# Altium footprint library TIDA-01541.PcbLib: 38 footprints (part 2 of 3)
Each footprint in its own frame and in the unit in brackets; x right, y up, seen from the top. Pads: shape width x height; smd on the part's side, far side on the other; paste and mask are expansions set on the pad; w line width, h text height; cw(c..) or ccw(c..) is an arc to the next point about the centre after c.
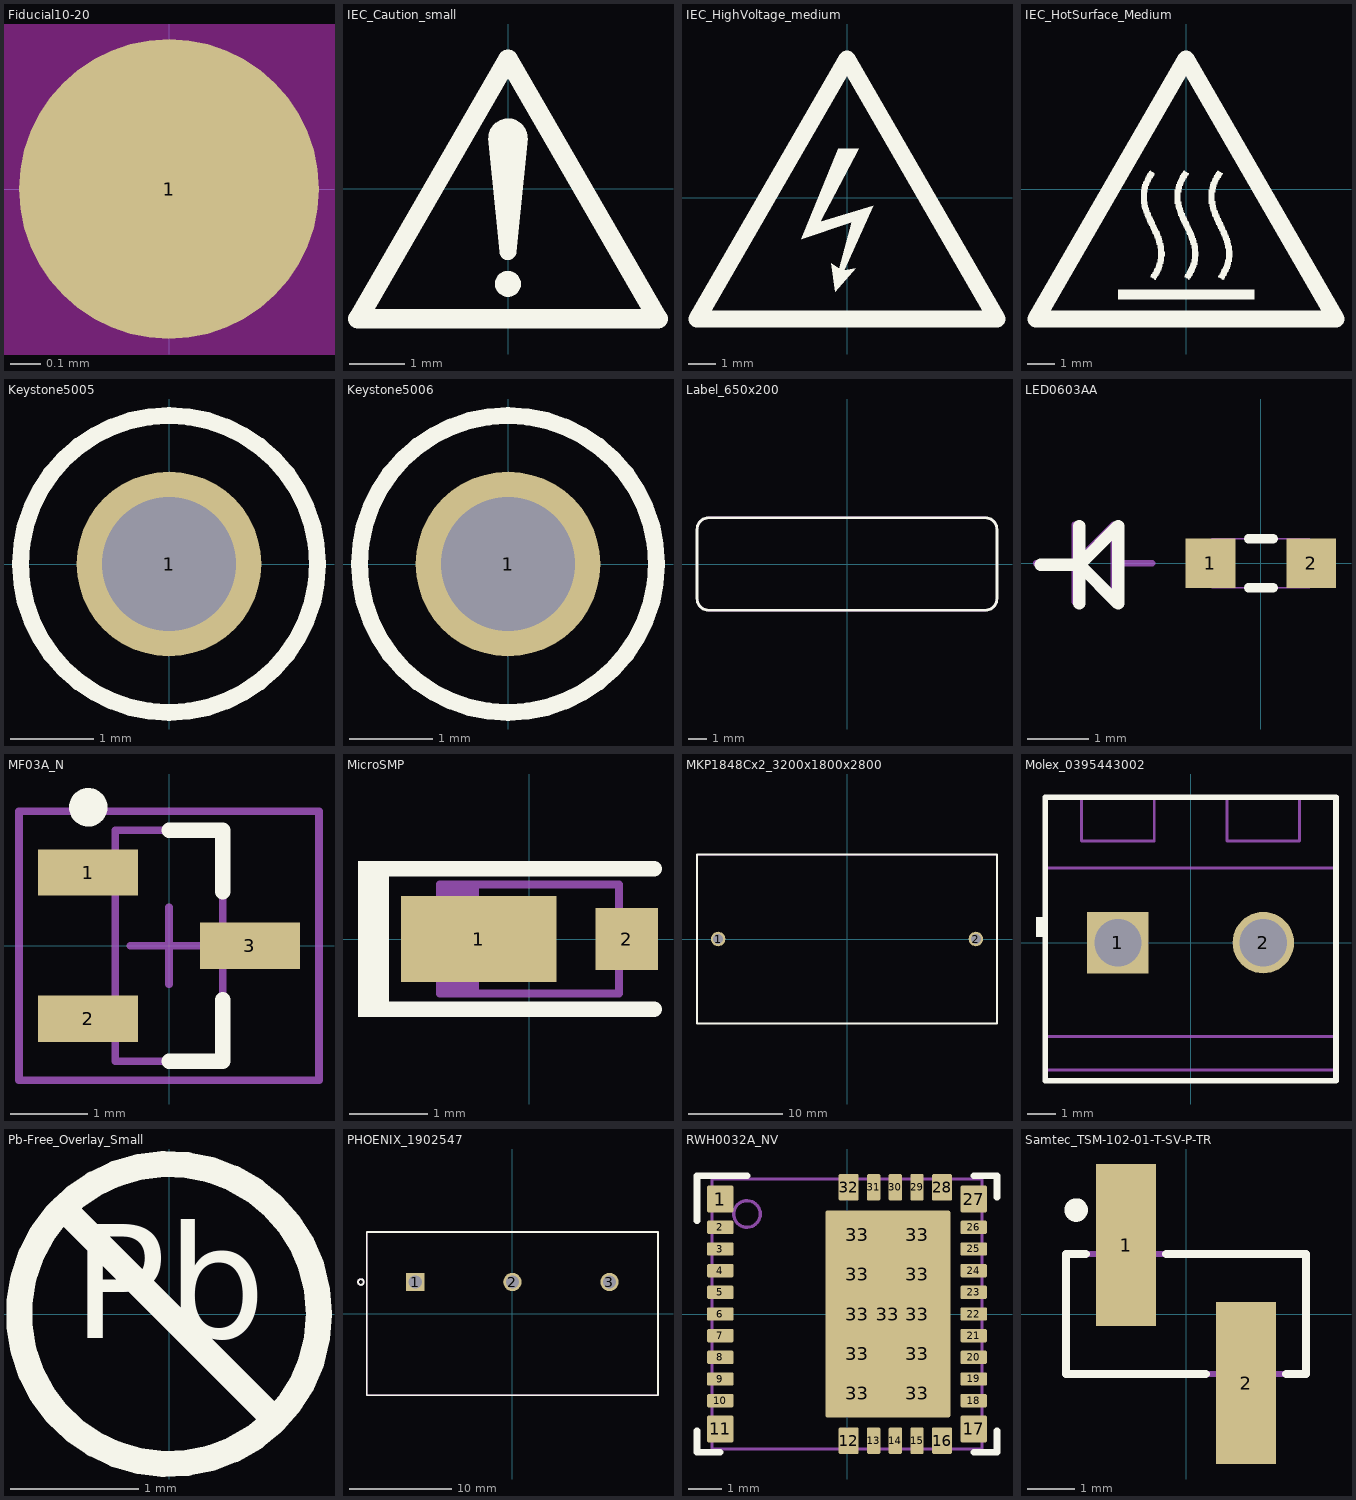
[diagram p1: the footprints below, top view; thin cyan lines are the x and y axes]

## Fiducial10-20 [mm]
pads (1):
  round 1 smd mask+0.5: 1(0,0)
Top Layer keep-out:
  circle w1.178: c0,0 r0.5

## IEC_Caution_small [mm]
height 8.382
Top Overlay:
  circle w0.254: c0,-1.143 r0.025
  circle w0.356: c0,0.914 r0.178
  circle w0.254: c0,-1.727 r0.108
  region: -0.356,0.914 0.356,0.914 0.152,-1.143 -0.152,-1.143
  lines w0.356: -2.718,-2.362 2.718,-2.362 0,2.345 -2.718,-2.362

## IEC_HighVoltage_medium [mm]
Top Overlay:
  region: -0.33,1.803 0.432,1.803 -0.991,-0.889 0.965,-0.305 -0.102,-2.667 0.33,-2.591 -0.432,-3.454 -0.584,-2.413 -0.279,-2.616 0.178,-0.914 -1.676,-1.524
  lines w0.635: -5.512,-4.458 0,5.089 5.512,-4.458 -5.512,-4.458

## IEC_HotSurface_Medium [mm]
height 8.382
Top Overlay:
  drawing of 7 lines, arcs and shapes, not listed

## Keystone5005 [mil] "Keystone Compact loops"
height 220
pads (1):
  round 87 hole 63: 1(0,0)
Top Overlay:
  circle w7.99: c0,0 r70
Mechanical 5:
  circle w5: c0,0 r70.71
  text ".Designator" at -55,-15 h30
3D body "Keystone_5005.stp": height 225.2, standoff -129.92, extent -63,-63 62.49,62.74

## Keystone5006 [mil] "Keystone Compact loops"
height 220
pads (1):
  round 87 hole 63: 1(0,0)
Top Overlay:
  circle w7.99: c0,0 r70
Mechanical 5:
  circle w5: c0,0 r70.71
  text ".Designator" at -55,-15 h30
3D body "Keystone_5006.stp": height 225.2, standoff -129.92, extent -63,-63 62.49,62.74

## Label_650x200 [mm] "Thermal Transfer Label"
height 0.025
Top Overlay:
  lines w0.152: -8.255,-1.905 ccw(c-7.62,-1.905) -7.62,-2.54 7.62,-2.54 ccw(c7.62,-1.905) 8.255,-1.905 8.255,1.905 ccw(c7.62,1.905) 7.62,2.54 -7.62,2.54 ccw(c-7.62,1.905) -8.255,1.905 -8.255,-1.905
Mechanical 5:
  lines w0.127: -8.255,-1.905 ccw(c-7.62,-1.905) -7.62,-2.54 7.62,-2.54 ccw(c7.62,-1.905) 8.255,-1.905 8.255,1.905 ccw(c7.62,1.905) 7.62,2.54 -7.62,2.54 ccw(c-7.62,1.905) -8.255,1.905 -8.255,-1.905
  text ".Designator" at -1.524,-0.508 h1.02
3D body: height 0.03, standoff 0, extent -8.256,-2.541 8.256,2.541

## LED0603AA [mil]
height 35.43
pads (2):
  rect 32x32 smd: 1(-32.48,0) 2(32.48,0)
Top Overlay:
  lines w6: -8,-15.75 8,-15.75 ; -8,15.75 8,15.75
  lines w8: -142,-1 -117,-1 ; -117,-26 -117,24 ; -117,-1 -92,-26 -92,24 -117,-1
Mechanical 5:
  lines w1: -31.5,-15.75 31.5,-15.75 31.5,15.75 -31.5,15.75 -31.5,-15.75
  lines w3.94: -145,0 -120,0 ; -120,-25 -120,25 ; -95,0 -70,0 ; -120,0 -95,25 -95,-25 -120,0
  text ".Designator" at 0,-5 h30

## MF03A_N [mm] "SOT23, 3-Leads, Body 2.9x1.3mm, Pitch 0.95mm, Lead Span 2.4mm, IPC Medium Density"
height 1.12
pads (3):
  rect 1.3x0.6 smd: 1(-1.05,0.95) 2(-1.05,-0.95) 3(1.05,0)
Top Overlay:
  circle w0.25: c-1.05,1.8 r0.125
  lines w0.2: 0,-1.5 0.7,-1.5 0.7,-0.7 ; 0,1.5 0.7,1.5 0.7,0.7
Mechanical 5:
  text ".Designator" at -0.051,-0.61 h0.76
Mechanical 13:
  lines w0.1: -0.7,-1.5 -0.7,1.5 0.7,1.5 0.7,-1.5 -0.7,-1.5
Mechanical 15:
  lines w0.1: -0.5,0 0.5,0 ; 0,-0.5 0,0.5 ; -1.95,-1.75 -1.95,1.75 1.95,1.75 1.95,-1.75 -1.95,-1.75
3D body: height 1.12, standoff 0, extent -0.7,-1.5 0.7,1.5

## MicroSMP [mm] "SMD, 2-Leads, Body 2.2x1.3mm"
height 0.73
pads (2):
  rect 2x1.1 smd: 1(-0.65,0)
  rect 0.8x0.8 smd: 2(1.25,0)
Top Overlay:
  rectangle: -2.2,-1 -1.9,1
  lines w0.2: 1.6,-0.9 -1.9,-0.9 -1.9,0.9 1.6,0.9
Mechanical 5:
  rectangle: -1.15,-0.7 -0.7,0.7
  lines w0.1: -0.7,-0.7 -0.7,0.7 ; -1.15,-0.7 -1.15,0.7 1.15,0.7 1.15,-0.7 -1.15,-0.7
  text ".Designator" at -0.279,-0.33 h0.76
3D body: height 0.75, standoff 0.73, extent -0.9,-0.7 -0.7,0.7
3D body: height 0.73, standoff 0, extent -1.15,-0.7 1.15,0.7

## MKP1848Cx2_3200x1800x2800 [mm] "TH, 2-Leads, Body 32x18mm"
height 28
pads (2):
  round 1.55 hole 1.05: 1(-13.75,0) 2(13.75,0)
Top Overlay:
  lines w0.2: -16,-9 16,-9 16,9 -16,9 -16,-9
Mechanical 5:
  lines w0.1: -16,-9 -16,9 16,9 16,-9 -16,-9
  text ".Designator" at 0.051,1.295 h0.76
3D body: height 28, standoff 0, extent -16,-9 16,9
3D body: height 0, standoff -3, extent 13.35,-0.4 14.15,0.4
3D body: height 0, standoff -3, extent -14.15,-0.4 -13.35,0.4

## Molex_0395443002 [mm] "Terminal Block, 5.08mm, 2x1, TH"
height 14.7
pads (2):
  rect 2.15x2.15 hole 1.65: 1(-2.54,0)
  round 2.15 hole 1.65: 2(2.54,0)
Top Overlay:
  rectangle: -5.4,0.2 -5.08,0.9
  lines w0.2: -5.08,-4.826 5.08,-4.826 5.08,-4.445 5.08,-3.281 5.08,2.61 5.08,5.08 3.81,5.08 1.27,5.08 -1.27,5.08 -3.81,5.08 -5.08,5.08 -5.08,2.61 -5.08,-3.281 -5.08,-4.445 -5.08,-4.826
Mechanical 5:
  lines w0.1: -5.08,-4.445 -5.08,-4.826 5.08,-4.826 5.08,-4.445 ; -5.08,-4.445 -5.08,-3.281 ; -5.08,-4.445 5.08,-4.445 ; -5.08,-3.281 -5.08,2.61 ; -5.08,-3.281 5.08,-3.281 ; -5.08,2.61 -5.08,5.08 -3.81,5.08 ; -5.08,2.61 5.08,2.61 ; -3.81,5.08 -1.27,5.08 ; -3.81,5.08 -3.81,3.556 -1.27,3.556 -1.27,5.08 ; -1.27,5.08 1.27,5.08 ; 1.27,5.08 3.81,5.08 ; 1.27,5.08 1.27,3.556 3.81,3.556 3.81,5.08 ; 3.81,5.08 5.08,5.08 5.08,2.61 ; 5.08,-4.445 5.08,-3.281 ; 5.08,-3.281 5.08,2.61
  text ".Designator" at -0.051,0.635 h1.02
3D body "395443002.stp": height 14.48, standoff -3.05, extent -5.08,-4.826 5.08,5.08

## Pb-Free_Overlay_Small [mm]
Top Overlay:
  circle w0.203: c0,0 r1.168
  lines w0.203: -0.826,0.826 0.826,-0.826
  text "Pb" at -0.752,-0.48 h1.52

## PHOENIX_1902547 [mm] "CONN, PCB TERMINAL BLOCK, 9.52 MM PITCH, 3POS, TH"
height 21.5
pads (3):
  rect 1.8x1.8 / inner round 1.8 / far side rect 1.8x1.8 hole 1.3: 1(-9.52,3.1)
  round 1.8 hole 1.3: 2(0,3.1) 3(9.52,3.1)
Top Overlay:
  circle w0.178: c-14.864,3.1 r0.279
  lines w0.178: -14.28,-8 -14.28,8 14.28,8 14.28,-8 -14.28,-8
Bottom Overlay:
  lines w0.178: -14.28,-6 -14.28,-8 -12.28,-8 ; -14.28,-4 -14.28,-2 ; -14.28,0 -14.28,2 ; -14.28,4 -14.28,6 ; -14.28,8 -12.28,8 ; -10.224,-8.076 -8.224,-8.076 ; -10.224,7.924 -8.224,7.924 ; -6.224,-8.076 -4.224,-8.076 ; -6.224,7.924 -4.224,7.924 ; -2.224,-8.076 -0.224,-8.076 ; -2.224,7.924 -0.224,7.924 ; 1.776,-8.076 3.776,-8.076 ; 1.776,7.924 3.776,7.924 ; 5.776,-8.076 7.776,-8.076 ; 5.776,7.924 7.776,7.924 ; 9.776,-8.076 11.776,-8.076 ; 9.776,7.924 11.776,7.924 ; 14.28,-8 14.28,-6 ; 14.28,-4 14.28,-2 ; 14.28,0 14.28,2 ; 14.28,4 14.28,6
Mechanical 5:
  circle w0.127: c-14.864,3.1 r0.279
  lines w0.127: -14.28,-8 -14.28,8 14.28,8 14.28,-8 -14.28,-8
  text ".Designator" at 0.762,3.556 h0.76
Mechanical 17:
  text "LEAD LENGTH IS 5.02 MM" at -10.922,-7.314 h1
3D body "1904150.stp": height 21.5, standoff -5, extent -14.275,-7.999 14.855,8.001

## RWH0032A_NV [mm] "VQFN, 32-Lead, Body 8x8mm"
height 0.9
pads (43):
  rrect12% 0.8x0.8 smd paste-0.02: 1(-3.8,3.45) 11(-3.8,-3.45) 17(3.8,-3.45) 27(3.8,3.45)
  rrect25% 0.8x0.4 smd: 2(-3.8,2.6) 3(-3.8,1.95) 4(-3.8,1.3) 5(-3.8,0.65) 6(-3.8,0) 7(-3.8,-0.65) 8(-3.8,-1.3) 9(-3.8,-1.95) 10(-3.8,-2.6) 18(3.8,-2.6) 19(3.8,-1.95) 20(3.8,-1.3) 21(3.8,-0.65) 22(3.8,0) 23(3.8,0.65) 24(3.8,1.3) 25(3.8,1.95) 26(3.8,2.6)
  rrect17% 0.6x0.8 smd: 12(0.05,-3.8) 16(2.85,-3.8) 28(2.85,3.8) 32(0.05,3.8)
  rrect25% 0.4x0.8 smd: 13(0.8,-3.8) 14(1.45,-3.8) 15(2.1,-3.8) 29(2.1,3.8) 30(1.45,3.8) 31(0.8,3.8)
  rrect50% 1.6x0.99 on Top Paste: 33(0.314,-2.38) 33(0.314,-1.19) 33(0.314,0) 33(0.314,1.19) 33(0.314,2.38) 33(2.114,-2.38) 33(2.114,-1.19) 33(2.114,0) 33(2.114,1.19) 33(2.114,2.38)
  rrect3% 3.75x6.2 smd paste-6.2: 33(1.225,0)
Top Overlay:
  lines w0.2: -4.5,-4.15 -4.5,-3.5 ; -4.5,2.8 -4.5,4.15 -3,4.15 ; -4.45,-4.15 -3.8,-4.15 ; 3.8,-4.15 4.45,-4.15 ; 3.8,4.15 4.45,4.15 ; 4.5,-4.15 4.5,-3.5 ; 4.5,3.5 4.5,4.15
Mechanical 5:
  circle w0.1: c-3,3 r0.4
  lines w0.1: -4.05,-4.05 -4.05,4.05 4.05,4.05 4.05,-4.05 -4.05,-4.05
  text ".Designator" at 0.563,0.549 h0.76
3D body "RWH0032A.stp": height 0.9, standoff 0, extent -4,-4 4,4

## Samtec_TSM-102-01-T-SV-P-TR [mil] "SMD, 2-Leads, Body 200x100mil"
height 380
pads (2):
  rect 50x135 smd: 1(-50,57.5) 2(50,-57.5)
Top Overlay:
  circle w9.84: c-91.54,86.61 r4.92
  lines w7: -83.5,50 -100,50 -100,-50 16.5,-50 ; -16.5,50 100,50 100,-50 83.5,-50
Mechanical 5:
  lines w5: -62.5,50 -62.5,76.5 ; -37.5,50 -37.5,76.5 ; 37.5,-50 37.5,-76.5 ; 62.5,-50 62.5,-76.5 ; -62.5,76.5 -37.5,76.5 ; -62.5,76.5 -55.22,96.5 -44.78,96.5 -37.5,76.5 ; 37.5,-76.5 44.78,-96.5 55.22,-96.5 62.5,-76.5 ; 37.5,-76.5 62.5,-76.5 ; -100,-50 100,-50 100,50 -100,50 -100,-50
  text ".Designator" at 78,12 h30
3D body "Samtec-TSM-102-01-T-SV-P.stp": height 380, standoff 0, extent -100,-96.5 100,96.5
